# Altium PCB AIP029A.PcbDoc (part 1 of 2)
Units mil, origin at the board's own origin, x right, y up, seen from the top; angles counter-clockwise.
Board outline 1259.84 x 1259.84 mil, 4 copper layers (Top Layer, MidLayer1, MidLayer2, Bottom Layer), stack 40.8 mil thick; 91 components, 74 nets, 317 pads, 128 vias.
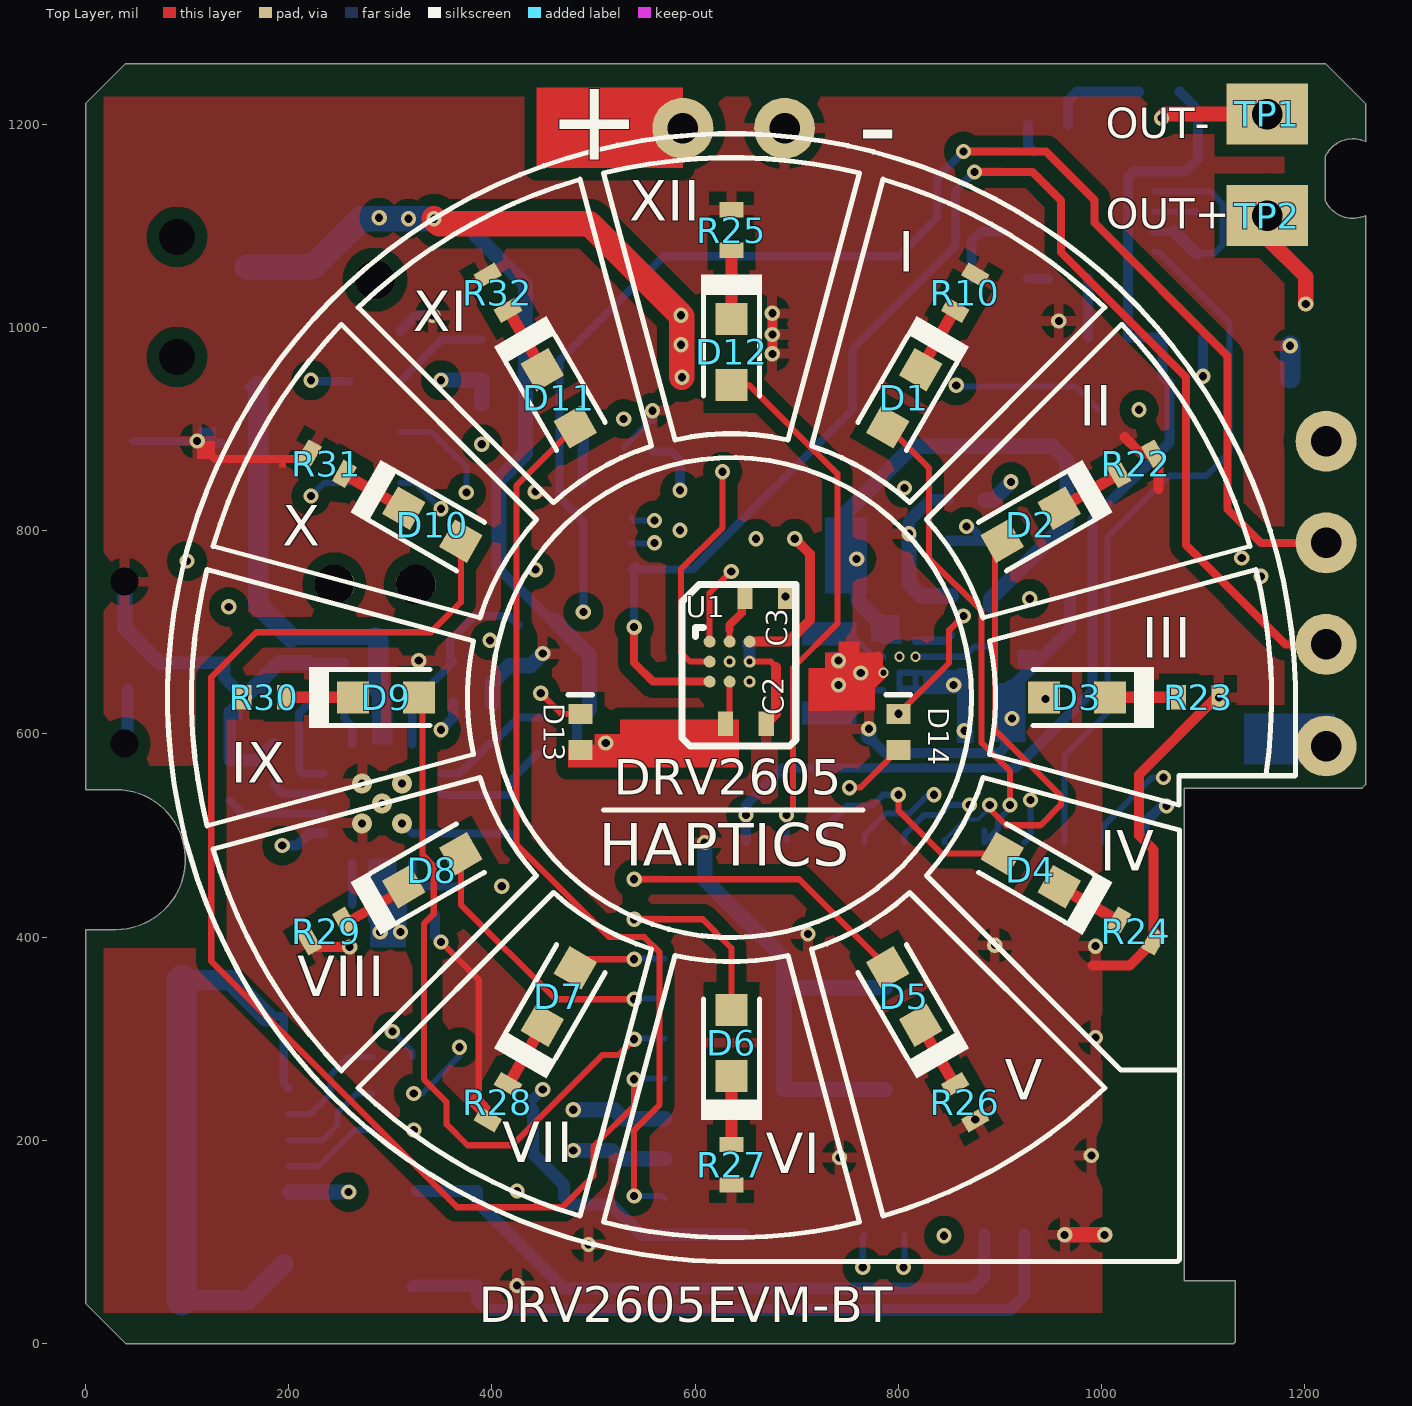
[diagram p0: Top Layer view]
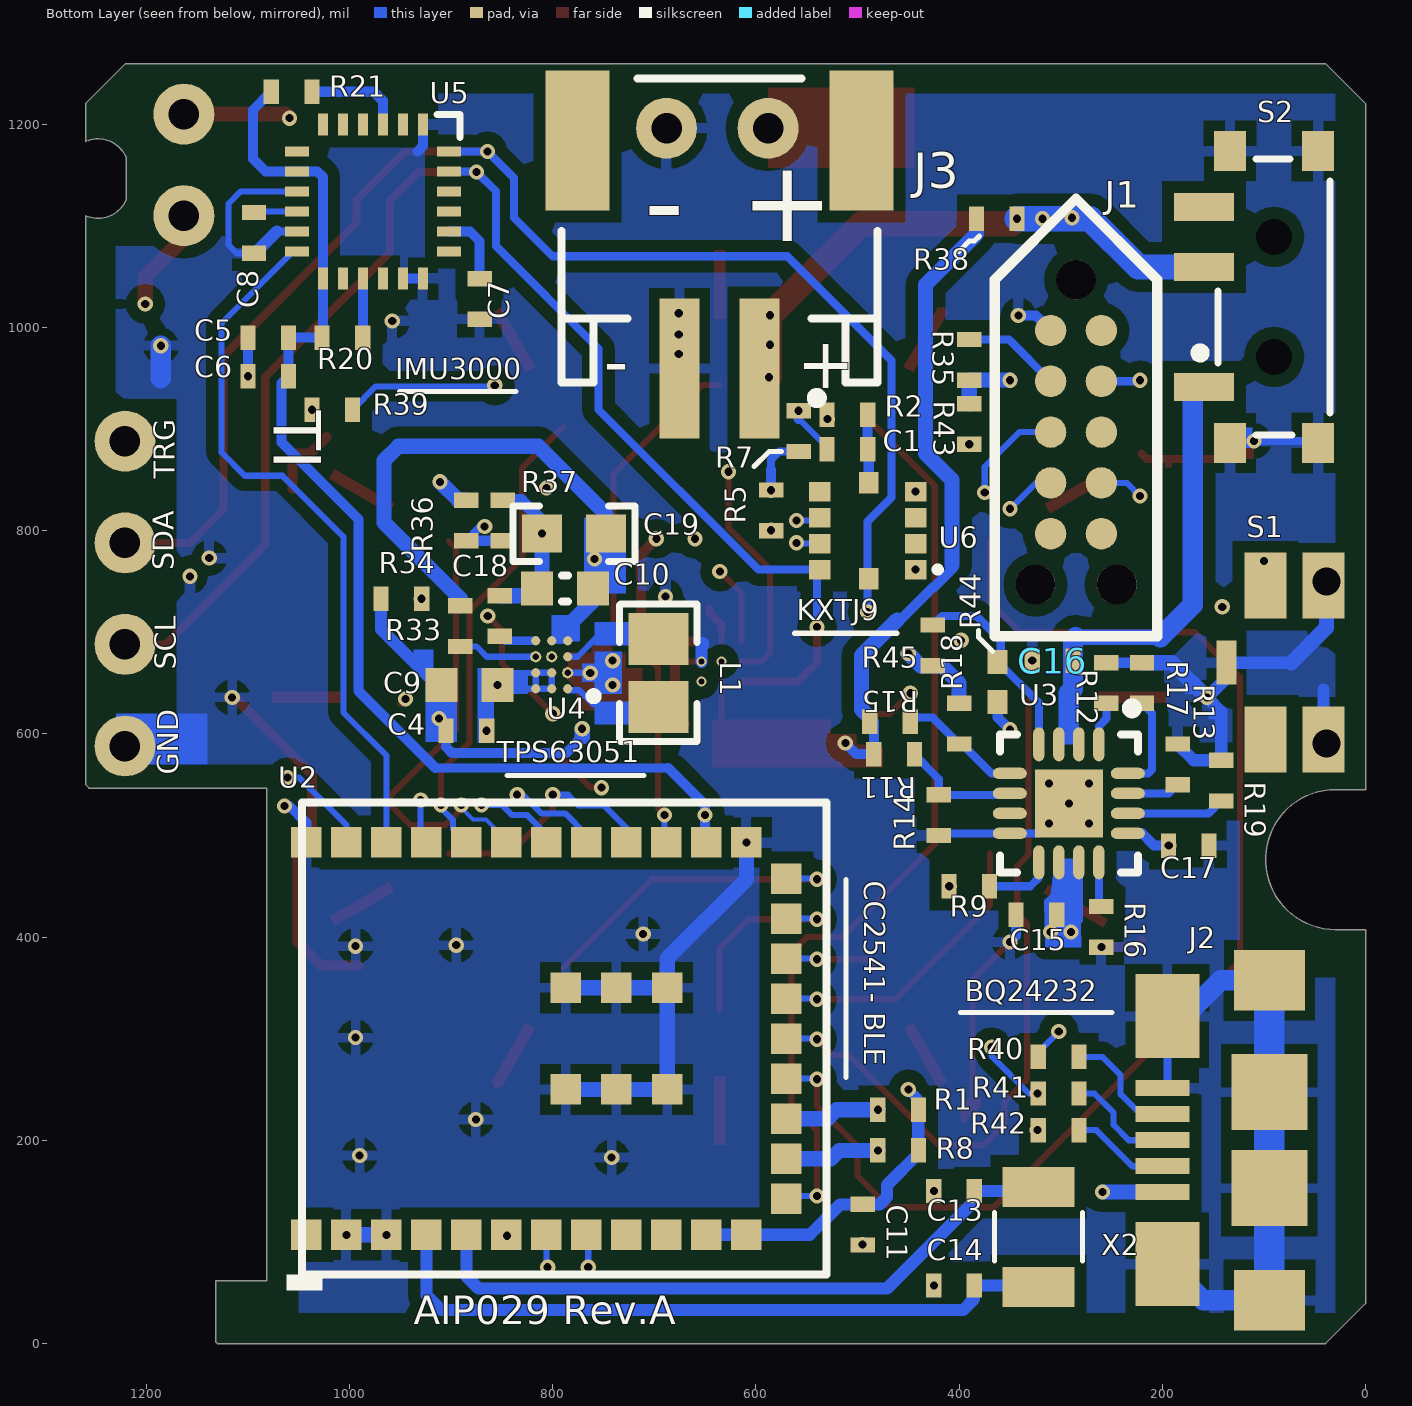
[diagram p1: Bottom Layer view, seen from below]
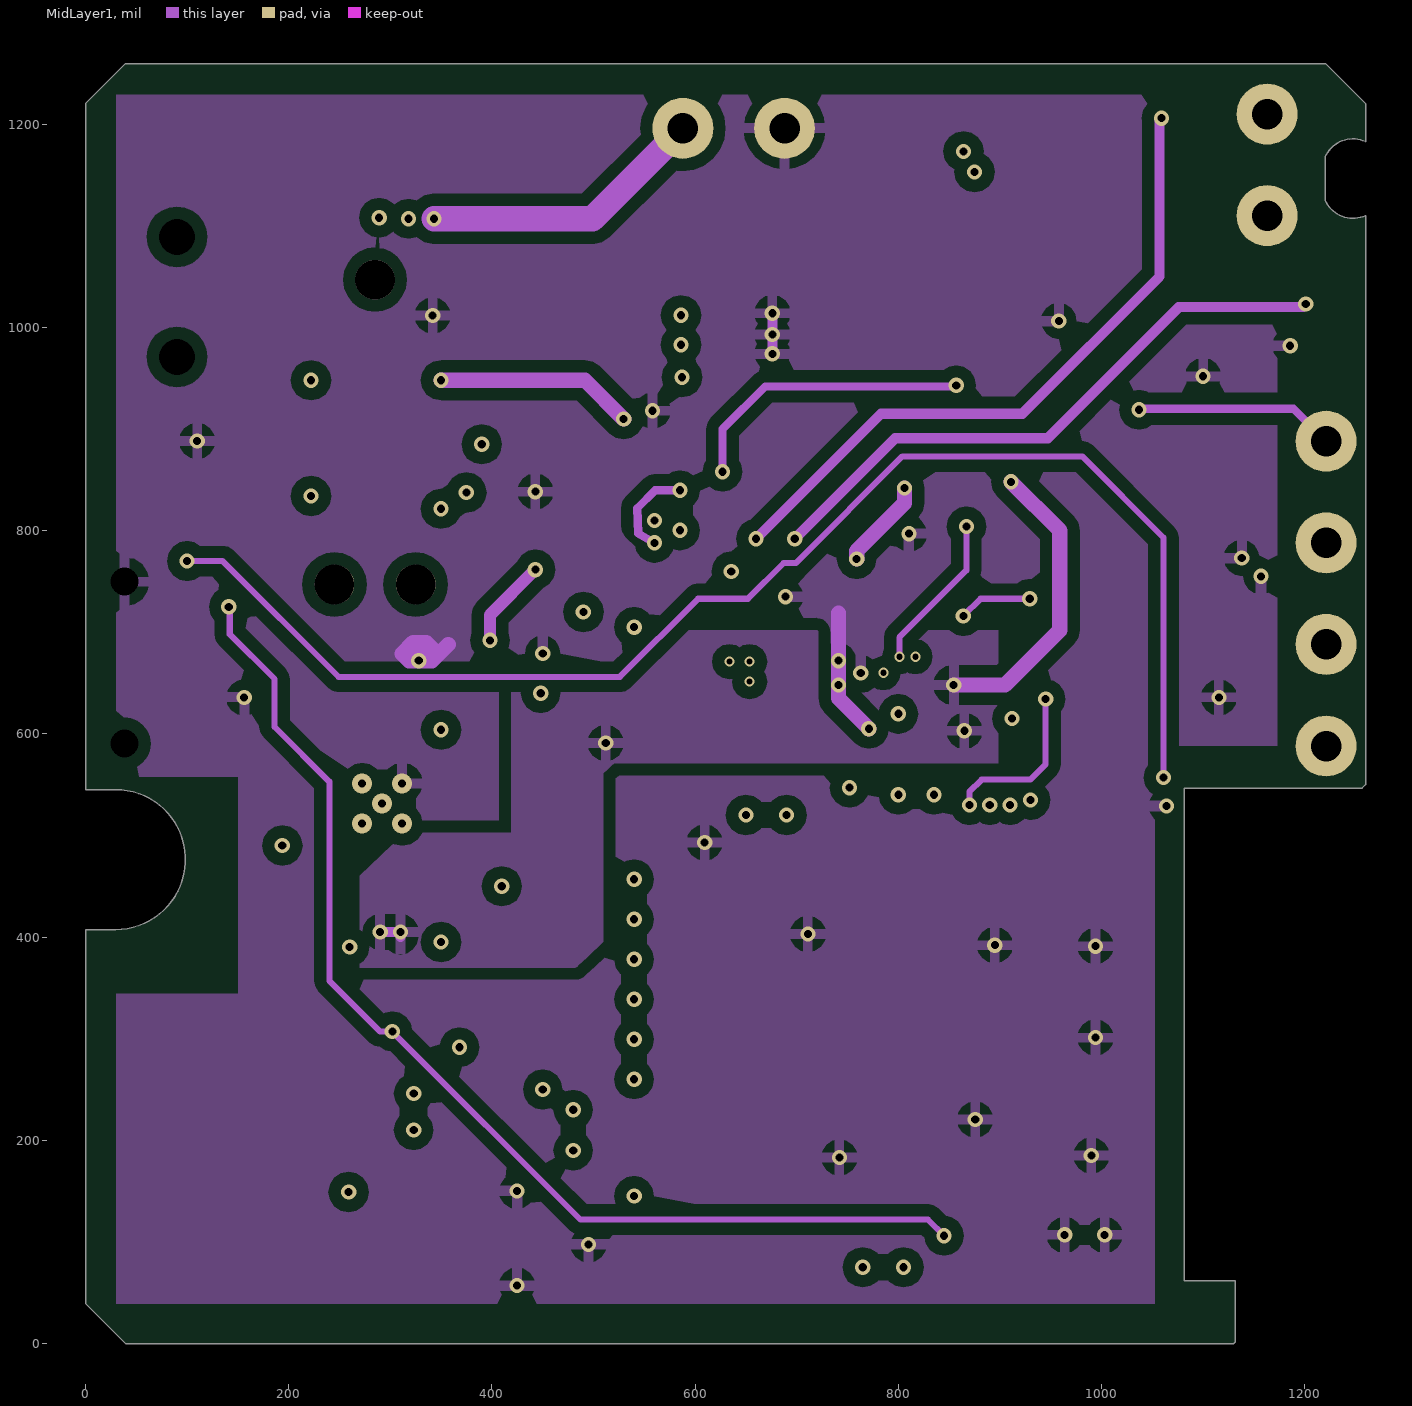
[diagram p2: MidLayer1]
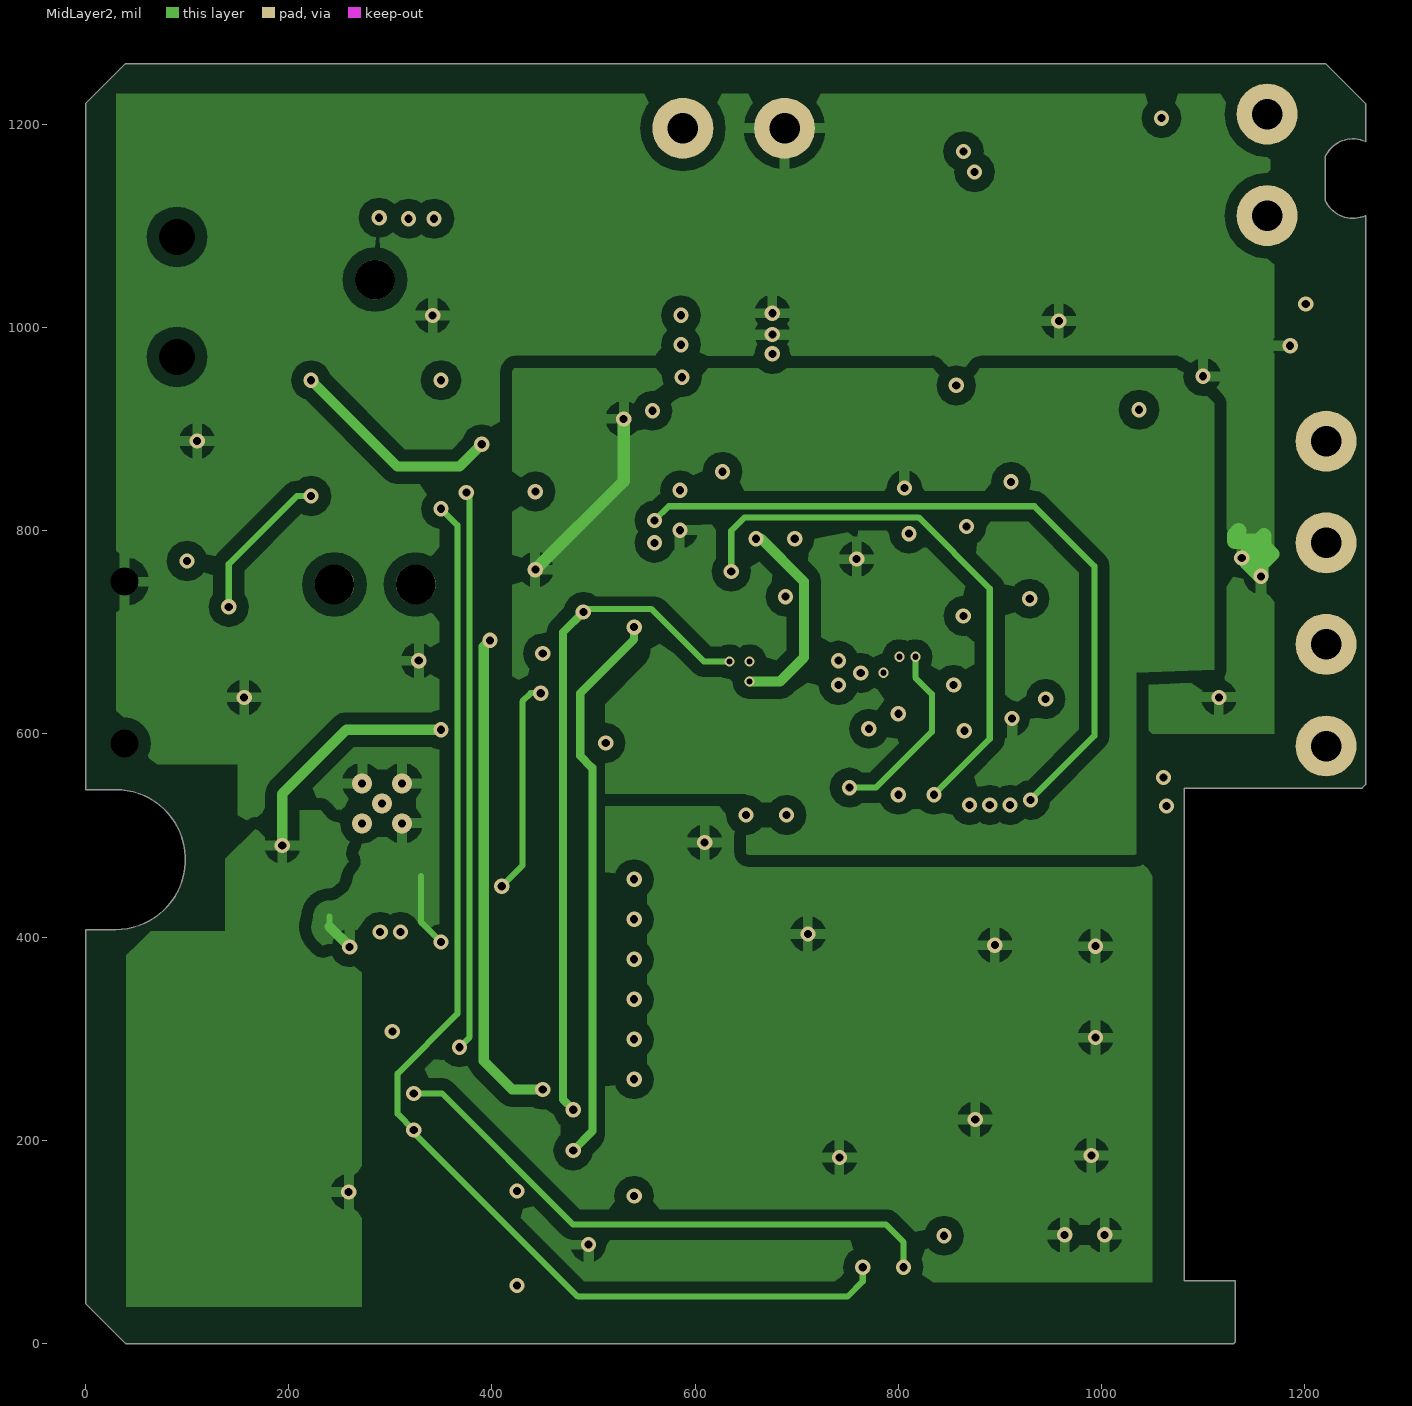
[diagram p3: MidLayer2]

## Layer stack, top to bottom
Top Layer: signal copper 1.4
Dielectric: core 10, FR-4, Dk 4.8
MidLayer1: signal copper 1.4
Dielectric: prepreg 12.6, FR-4, Dk 4.8
MidLayer2: signal copper 1.4
Dielectric: core 12.6, FR-4, Dk 4.8
Bottom Layer: signal copper 1.4

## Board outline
39.37,-0.09 1130.08,-0.09 1131.6,1.44 1131.6,61.6 1081.6,61.6 1081.6,546.6 1256.44,546.6 1259.84,550 1259.84,1110.04 cw(c1247.53,1137.6) 1219.97,1125.29 1219.97,1167.75 cw(c1247.53,1155.44) 1259.84,1183 1259.84,1220.39 1220.47,1259.76 39.37,1259.76 0,1220.39 0,545.19 29.53,545.19 cw(c29.53,476.29) 29.53,407.4 0,407.4 0,39.28

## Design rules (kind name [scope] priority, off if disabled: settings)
AcuteAngle [All] p1: minimum=4.50000000000000E+0001 checktracksonly=FALSE
AssemblyTestPointUsage [All] p1: valid=2
Clearance Clearance_BoardEdge_MountingHoles [OnCopper and InComponentClass('Mounting Holes') vs IsKeepOut] p1: gap=40
Clearance Clearance_BoardEdge_Poly [OnCopper and InPoly vs IsKeepOut] p2: gap=25
Clearance Clearance_BoardEdge [OnCopper and Not InComponentClass('Logo') and not InComponentClass('FiducialMark') and not InRegion(1000,500,4000,800) and Not IsKeepout vs IsKeepOut] p3: gap=75
Clearance Clearance_Poly [InPolygon] p4: gap=8
Clearance [All vs All and not S1] p5: gap=5
ComponentClearance ComponentClearance_1 [All] p1: gap=0 collisioncheckmode=3 verticalgap=0 showdistances=FALSE
ComponentClearance ComponentClearance_Shunt [InComponentClass('Header') vs InComponentClass('Shunt')] p2: gap=0 collisioncheckmode=3 verticalgap=0 showdistances=FALSE
ComponentClearance ComponentClearance_Logo [InComponentClass('Logo')] p3: gap=50 collisioncheckmode=3 verticalgap=10 showdistances=FALSE
ComponentClearance ComponentClearance_ScrewToNut [(HasFootprint('NY PMS 440 0025 PH')) vs (HasFootprint('Keystone_1902C'))] p4: gap=5 collisioncheckmode=3 verticalgap=10 showdistances=FALSE
ComponentClearance ComponentClearance_MountingHoles [InComponentClass('Mounting Holes')] p5: gap=250 collisioncheckmode=3 verticalgap=100000 showdistances=FALSE
ComponentClearance ComponentClearance_SmallPassives [HasFootprint('0201*') or HasFootprint('0402*') or HasFootprint('0508') or HasFootprint('0603*') or HasFootprint('0612') or HasFootprint('0805*') or HasFootprint('0815*') or HasFootprint('0830*') or HasFootprint('1206*') or HasFootprint('1210*') or HasFootprint('1808*') or HasFootprint('1812*') or HasFootprint('1825*') or HasFootprint('2010*') or HasFootprint('2220*') or HasFootprint('2225*') or HasFootprint('2512*') or HasFootprint('2728*') or HasFootprint('3518*') vs HasFootprint('0201*') or HasFootprint('0402*') or HasFootprint('0508') or HasFootprint('0603*') or HasFootprint('0612') or HasFootprint('0805*') or HasFootprint('0815*') or HasFootprint('0830*') or HasFootprint('1206*') or HasFootprint('1210*') or HasFootprint('1808*') or HasFootprint('1812*') or HasFootprint('1825*') or HasFootprint('2010*') or HasFootprint('2220*') or HasFootprint('2225*') or HasFootprint('2512*') or HasFootprint('2728*') or HasFootprint('3518*')] p6: gap=5 collisioncheckmode=3 verticalgap=-70 showdistances=FALSE
ComponentClearance ComponentClearance_THtoSMT [IsThruComponent vs IsSMTComponent] p7: gap=5 collisioncheckmode=3 verticalgap=5 showdistances=FALSE
ComponentClearance ComponentClearance_THtoTH [IsThruComponent vs IsThruComponent] p8: gap=5 collisioncheckmode=3 verticalgap=10 showdistances=FALSE
DiffPairsRouting [All] p1: maxlimit=100 minlimit=10 mostfreqgap=10 maxuncoupledlength=1000
FabricationTestPointUsage TestPointUsage [All] p1: valid=2 allowmultiple=FALSE
FabricationTestpoint Testpoint [All] p1: side=3 testpointundercomponent=TRUE minsize=40 maxsize=100 preferedsize=60 minholesize=0 maxholesize=40 preferedholesize=32 testpointgrid=1 allowsidetop=TRUE allowsidebottom=TRUE usegrid=TRUE gridtolerance=0.01
FanoutControl Fanout_LCC [IsLCC] p1: bgadir=Out bgaviamode=Centered fanoutstyle=Auto fanoutdirection=Alternating viagrid=1 // Fanout_LCC (Default Rule)
FanoutControl Fanout_BGA [IsBGA] p2: bgadir=Out bgaviamode=Centered fanoutstyle=Auto fanoutdirection=Alternating viagrid=1 // Fanout_BGA (Default Rule)
FanoutControl Fanout_Default [All] p4: bgadir=Out bgaviamode=Centered fanoutstyle=Auto fanoutdirection=Alternating viagrid=1 // Fanout_Default (Default Rule)
FanoutControl Fanout_Small [(CompPinCount < 5)] p5: bgadir=Out bgaviamode=Centered fanoutstyle=Auto fanoutdirection=OutThenIn viagrid=1 // Fanout_Small (Default Rule)
HoleSize [All] p1: absolutevalues=TRUE maxlimit=251 minlimit=3 maxpercent=80.000 minpercent=20.000
HoleToHoleClearance [All] p1: gap=9 allowstackedmicrovias=TRUE
MinimumAnnularRing MinimumAnnularRing_ThermalPadVias [IsVia and InAnyComponent] p1: minimumring=5.91
MinimumAnnularRing [All] p2: minimumring=2
MinimumSolderMaskSliver MinimumSolderMaskSliver_Logo [InComponentClass('Logo') vs InComponentClass('Logo')] p1: minsoldermaskwidth=0.7
MinimumSolderMaskSliver [All] p2: minsoldermaskwidth=4
PlaneClearance [All] p1: clearance=12
PlaneConnect [All] p1: planeconnectstyle=Relief reliefexpansion=10 reliefentries=4 reliefconductorwidth=10 reliefairgap=10
PolygonConnect [All] p1: connectstyle=Relief reliefconductorwidth=10 reliefentries=4 polygonreliefangle="90 Angle" airgapwidth=10
RoutingVias ThermalPadVias [IsVia and InAnyComponent] p1: holewidth=7.87 width=19.68 viastyle="Through Hole" minholewidth=7.87 minwidth=19.68 maxholewidth=12.99 maxwidth=23.62
RoutingVias [All] p2: holewidth=16 width=34 viastyle="Through Hole" minholewidth=5 minwidth=10 maxholewidth=40 maxwidth=65
SMDToCorner [All] p1: distance=1000
ShortCircuit [All] p1: allowed=TRUE
SilkToSilkClearance [All] p1: silktosilkclearance=0
SilkscreenOverComponentPads [All] p1: minsilkscreentomaskgap=-1
SolderMaskExpansion [All] p1: expansion=1
Width [All] p1: maxlimit=100 minlimit=3 preferedwidth=10 checkconnectedcopper=TRUE
11 further rules are at their usual default settings.

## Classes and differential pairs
component class AIP029A_Hardware: !PCB H1 H2 H3 H4 ZZ1 ZZ2
component class AssemblyNote: ZZ1 ZZ2

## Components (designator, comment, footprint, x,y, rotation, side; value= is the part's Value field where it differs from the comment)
C1 "GRM155R71C104KA88D" 0402S 510,880 r180 bottom
C2 "GRM155R71C104KA88D" 0402S 650,610 r0 top
C3 "GRM155R61A105KE15D" 0402S 669,735 r0 top
C4 "C1005X5R0J475M050BC" 0402S 885,603 r0 bottom
C5 "GRM155R71A104KA01D" 0402S 1080,990 r180 bottom
C6 "GRM155R71E103KA01D" 0402S 1080,952 r0 bottom
C7 "GRM155R71H222KA01D" 0402S 872,1028 r270 bottom
C8 "GRM155R71A104KA01D" 0402S 1094,1093 r270 bottom
C9 "C1608X5R1A106M" 0603L 882,648 r0 bottom
C10 "C1608X5R1A106M" 0603L 788,743 r0 bottom
C11 "C1005X7R1H104K" 0402S 495,117 r90 bottom
C13 "GRM1555C1H220JA01D" 0402S 405,150 r180 bottom
C14 "GRM1555C1H220JA01D" 0402S 405,57 r180 bottom
C15 "GRM155R61A475M" 0402S 324,422 r0 bottom
C16 "GRM155R61A475M" 0402S 308,672 r0 bottom
C17 "GRM155R61A105KE15D" 0402S 174,490 r180 bottom
C18 "C1005C0G1E102J" 0402S 852,716 r90 bottom
C19 "GRM188R60J476M" 0603 779,797 r0 bottom
D1 "SML312WBCW1" LED_SML 805.82,930.31 r60 top
D2 "SML312WBCW1" LED_SML 930.27,805.87 r30 top
D3 "SML312WBCW1" LED_SML 975.82,635.87 r0 top
D4 "SML312WBCW1" LED_SML 930.27,465.87 r330 top
D5 "SML312WBCW1" LED_SML 805.82,341.42 r300 top
D6 "SML312WBCW1" LED_SML 635.82,295.87 r270 top
D7 "SML312WBCW1" LED_SML 465.82,341.42 r240 top
D8 "SML312WBCW1" LED_SML 341.37,465.87 r210 top
D9 "SML312WBCW1" LED_SML 295.82,635.87 r180 top
D10 "SML312WBCW1" LED_SML 341.37,805.87 r150 top
D11 "SML312WBCW1" LED_SML 465.82,930.31 r120 top
D12 "SML312WBCW1" LED_SML 635.82,975.87 r90 top
D13 "SML-P12DTT86" LED_SMLP12_ORANGE 487,602 r90 top
D14 "SML-P12YTT86" LED_SMLP12_Yellow 800,602 r90 top
J1 "Used in BOM report" PCBComponent_1 364.99,696 r180 bottom
J2 "ZX62-B-5PA(11)" CONN_USB_micro_ZX62-B-5PA 200,200 r90 bottom
J3 "S2B-PH-SM4-TB(LF)(SN)" JST_S2B-PH-SM4-TB 635.82,1075.87 r0 bottom
L1 "LQM21PN1R0MC0D" 0805 696,660 r90 bottom
R1 "CRCW040210K0FKED" 0402S 460,230 r180 bottom
R2 "CRCW04020000Z0ED" 0402S 510,914 r0 bottom
R5 "CRCW04020000Z0ED" 0402S 585,820 r270 bottom
R7 "CRCW04020000Z0ED" 0402S 558,898 r270 bottom
R8 "CRCW040210K0FKED" 0402S 460,190 r180 bottom
R9 "CRCW04021K50FKED" 0402S 390,450 r0 bottom
R10 "CRCW040275R0FKED" 0402S 865.82,1034.24 r240 top
R11 "CRCW04020000Z0ED" 0402S 464,580 r0 bottom
R12 "CRCW040210K0FKED" 0402S 255,650 r270 bottom
R13 "CRCW04027K32FKED" 0402S 185,570 r270 bottom
R14 "CRCW04020000Z0ED" 0402S 420,520 r90 bottom
R15 "CRCW04020000Z0ED" 0402S 468,612 r0 bottom
R16 "CRCW040214K7FKED" 0402S 260,410 r90 bottom
R17 "CRCW04028K66FKED" 0402S 220,650 r270 bottom
R18 "CRCW04020000Z0ED" 0402S 400,610 r270 bottom
R19 "CRCW04020000Z0ED" 0402S 142,554 r270 bottom
R20 "CRCW04020000Z0ED" 0402S 1007,990 r180 bottom
R21 "CRCW04020000Z0ED" 0402S 1057,1232 r0 bottom
R22 "CRCW040275R0FKED" 0402S 1034.19,865.87 r210 top
R23 "CRCW040275R0FKED" 0402S 1095.82,635.87 r180 top
R24 "CRCW040275R0FKED" 0402S 1034.19,405.87 r150 top
R25 "CRCW040275R0FKED" 0402S 635.82,1095.87 r270 top
R26 "CRCW040275R0FKED" 0402S 865.82,237.49 r120 top
R27 "CRCW040275R0FKED" 0402S 635.82,175.87 r90 top
R28 "CRCW040275R0FKED" 0402S 405.82,237.49 r60 top
R29 "CRCW040275R0FKED" 0402S 237.45,405.87 r30 top
R30 "CRCW040275R0FKED" 0402S 175.82,635.87 r0 top
R31 "CRCW040275R0FKED" 0402S 237.45,865.87 r330 top
R32 "CRCW040275R0FKED" 0402S 405.82,1034.24 r300 top
R33 "CRCW040210K0FKED" 0402S 891,706 r90 bottom
R34 "CRCW04021K50FKED" 0402S 949,733 r180 bottom
R35 "CRCW04020000Z0ED" 0402S 390,968 r270 bottom
R36 "CRCW04020000Z0ED" 0402S 885,810 r90 bottom
R37 "CRCW04020000Z0ED" 0402S 849,810 r270 bottom
R38 "CRCW04020000Z0ED" 0402S 363,1107 r0 bottom
R39 "CRCW04020000Z0ED" 0402S 1017,919 r0 bottom
R40 "CRCW04020000Z0ED" 0402S 302,282 r0 bottom
R41 "CRCW04020000Z0ED" 0402S 302,246 r0 bottom
R42 "CRCW04020000Z0ED" 0402S 302,210 r0 bottom
R43 "CRCW04020000Z0ED" 0402S 390,905 r90 bottom
R44 "CRCW04020000Z0ED" 0402L 362,651 r270 bottom
R45 "CRCW04020000Z0ED" 0402S 426,687 r90 bottom
S1 "PTS840 PM SMTR LFS" "SW_PTS840 P" 70,670 r90 bottom locked
S2 "EG1257" SW_EG1257 90,1030 r90 bottom
TP1 "" DUMMY-PAD 1163,1210 r180 top
TP2 "" DUMMY-PAD 1163,1110 r180 top
U1 "DRV2605YZF" YZF0009ADAD 633.96,671.04 r0 top
U2 "450-0103" TiWi-uB1 570,300 r90 bottom
U3 "BQ24232RGTR" RGT0016C 292.02,531.6 r270 bottom
U4 "TPS63051YFF" YFF0012AFAF 801,668 r0 bottom
U5 "IMU-3000" QFN50P400X400X95-24N 977,1124 r270 bottom
U6 "KXTJ9-1007" LGA3X3MM_0.65 490,800 r0 bottom
X2 "NX3215SA-32.768K-STD-MUS-2" XTAL_NX3215SA 322,105 r270 bottom
ZZ1 "CE Logo" AssemblyNote 212,2423 r0 top
ZZ2 "These assemblies are ESD sensitive, ESD precautions shall be observed." AssemblyNote 193,2235 r0 top

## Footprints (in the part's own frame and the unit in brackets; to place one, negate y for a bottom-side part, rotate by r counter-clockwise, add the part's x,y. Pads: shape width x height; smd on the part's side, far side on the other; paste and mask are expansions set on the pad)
0402L [mm] "0402 from SM-752 data"
  rect 0.6x0.5 smd: 1(-0.5,0) 2(0.5,0)
  body extent -0.55,-0.3 0.55,0.3, height 0.6
0402S [mil] "Based on C0402S footprint from PADS legacy"
  rect 15x24 smd: 1(-20,0) 2(20,0)
  body extent -22,-12 22,12, height 24
0603 [mm] "0603 from SM-752 data"
  rect 1x0.95 smd: 1(-0.8,0) 2(0.8,0)
  silkscreen extent -1.52,-0.69 1.52,0.69, body extent -0.87,-0.47 0.87,0.47, height 0.85
0603L [mm] "0603 from SM-752 data"
  rect 0.8x0.85 smd: 1(-0.7,0) 2(0.7,0)
  body extent -0.87,-0.47 0.87,0.47, height 0.85
0805 [mm] "0805 from SM-752 data"
  rect 1.3x1.5 smd: 1(-0.85,0) 2(0.85,0)
  silkscreen extent -1.72,-0.97 1.72,0.97, body extent -1.1,-0.72 1.1,0.72, height 1.1
AssemblyNote [mil] "Assembly Note"
CONN_USB_micro_ZX62-B-5PA [mm] "Hirose"
  rect 0.4x1.35 smd: 1(-1.3,0) 2(-0.65,0) 3(0,0) 4(0.65,0) 5(1.3,0)
  rect 1.9x1.9 smd: 6(-1.2,-2.675) 7(1.2,-2.675)
  rect 1.524x1.778 smd: 8(-4,-2.675) 9(4,-2.675)
  rect 2.1x1.6 smd: 10(-3.1,-0.125) 11(3.1,-0.125)
  body extent -3.75,-5.32 3.75,0.18, height 2.55
DUMMY-PAD [mil]
  rect 80x60 smd: 1(0,0)
JST_S2B-PH-SM4-TB [mm] "JST Sales America Inc"
  rect 1x3.5 smd paste+0: 1(-1,2.95)
  rect 1x3.5 smd: 2(1,2.95)
  rect 1.6x3.5 smd paste+0 mask+0.05: M1(-3.55,-2.75) M2(3.55,-2.75)
  silkscreen extent -3.95,-4.3 3.95,3.79, body extent -3.95,-4.3 3.95,4.3, height 5.62
LED_SML [mm] "Rohm"
  rect 0.8x0.8 smd: 1(-0.825,0) 2(0.825,0)
  silkscreen extent -1.1,-0.76 1.93,0.76, body extent -0.8,-0.4 0.8,0.4, height 0.9
LED_SMLP12_ORANGE [mm] "Rohm Semiconductor"
  rect 0.5x0.6 smd mask+0.08: 1(-0.45,0) 2(0.45,0)
  silkscreen extent 0.92,-0.3 0.92,0.3, body extent -0.55,-0.35 0.55,0.35, height 0.25
LED_SMLP12_Yellow [mm] "Rohm Semiconductor"
  rect 0.5x0.6 smd mask+0.08: 1(-0.45,0) 2(0.45,0)
  silkscreen extent 0.92,-0.3 0.92,0.3, body extent -0.55,-0.35 0.55,0.35, height 0.25
LGA3X3MM_0.65 [mm] "KIONIX"
  rect 0.54x0.49 smd paste-0.092 mask-0.07: 1(-1.2,0.975) 2(-1.2,0.325) 3(-1.2,-0.325) 4(-1.2,-0.975) 6(1.2,-0.975) 7(1.2,-0.325) 8(1.2,0.325) 9(1.2,0.975)
  rect 0.49x0.54 smd paste-0.092 mask-0.07: 5(-0.025,-1.2) 10(-0.025,1.2)
  silkscreen extent -1.77,0.95 -1.73,1, body extent -1.55,-1.55 1.55,1.55, height 1.02
PCBComponent_1 [mil]
  round 30.98 smd paste+0 mask+1.5: 1(55.04,301) 2(55.04,251) 3(55.04,201) 4(55.04,151) 5(55.04,101) 6(105.04,101) 7(105.04,151) 8(105.04,201) 9(105.04,251) 10(105.04,301)
  round 39.02 hole 39.02 unplated mask+1.5: ""(40.08,51) ""(80.04,351) ""(120,51)
  silkscreen extent 0,0 160,431
QFN50P400X400X95-24N [mm] "QFN, 24-Leads, Body 4.1x4.1mm (max), Pitch 0.50mm"
  rect 0.55x0.25 smd mask+0.05: 1(-1.925,1.25) 2(-1.925,0.75) 3(-1.925,0.25) 4(-1.925,-0.25) 5(-1.925,-0.75) 6(-1.925,-1.25) 13(1.925,-1.25) 14(1.925,-0.75) 15(1.925,-0.25) 16(1.925,0.25) 17(1.925,0.75) 18(1.925,1.25)
  rect 0.25x0.6 smd mask+0.05: 7(-1.25,-1.9) 8(-0.75,-1.9) 9(-0.25,-1.9) 10(0.25,-1.9) 11(0.75,-1.9) 12(1.25,-1.9) 19(1.25,1.9) 20(0.75,1.9) 21(0.25,1.9) 22(-0.25,1.9) 23(-0.75,1.9) 24(-1.25,1.9)
  silkscreen extent -2.17,1.6 -1.6,2.17, body extent -2.05,-2.05 2.05,2.05, height 0.95
RGT0016C [mm] "QFN, 16-Leads, Body 3x3mm, Pitch 0.5mm, Thermal Pad 1.7x1.7mm, TI Recommended"
  oval 0.85x0.28 smd paste-0.025: 1(-1.475,0.75) 2(-1.475,0.25) 3(-1.475,-0.25) 4(-1.475,-0.75) 9(1.475,-0.75) 10(1.475,-0.25) 11(1.475,0.25) 12(1.475,0.75)
  oval 0.28x0.85 smd paste-0.025: 5(-0.75,-1.475) 6(-0.25,-1.475) 7(0.25,-1.475) 8(0.75,-1.475) 13(0.75,1.475) 14(0.25,1.475) 15(-0.25,1.475) 16(-0.75,1.475)
  rect 1.7x1.7 smd paste-0.85 mask+0.07: 17(0,0)
  silkscreen extent -2.5,-1.73 1.73,1.73, body extent -1.57,-1.57 1.58,1.58, height 1
SW_EG1257 [mm] "E-SWITCH"
  rect 0.7x1.5 smd: 1(-2.25,1.75) 2(0.75,1.75) 3(2.25,1.75)
  rect 1x0.8 smd: 4(-3.65,-1.1) 5(-3.65,1.1) 6(3.65,-1.1) 7(3.65,1.1)
  round 0 hole 0.9 unplated: MH-1(-1.5,0) MH-1(1.5,0)
  silkscreen extent -3.45,-1.4 3.45,1.97, body extent -3.9,-2.85 3.9,2.2, height 1.6
"SW_PTS840 P" [mm] "C&K"
  rect 1.65x1.05 smd: 1(-1.925,0.725) 2(1.925,0.725) 3(-1.925,-0.725) 4(1.925,-0.725)
  rect 1.1x0.5 smd: 5(0,1.7)
  round 0 hole 0.7: MH1(-2.025,-0.8) MH2(2.025,-0.8)
  body extent -1.75,-2.1 1.75,1.45, height 1.35
TiWi-uB1 [mm] "Bluetooth Module"
  rect 0.76x0.76 smd: 1(-4.905,12) 2(-4.905,11) 3(-4.905,10) 4(-4.905,9) 5(-4.905,8) 6(-4.905,7) 7(-4.905,6) 8(-4.905,5) 9(-4.905,4) 10(-4.905,3) 11(-4.905,2) 12(-4.905,1) 13(-4,0) 14(-3,0) 15(-2,0) 16(-1,0) 17(0,0) 18(1,0) 19(2,0) 20(3,0) 21(4,0) 22(4.905,1) 23(4.905,2) 24(4.905,3) 25(4.905,4) 26(4.905,5) 27(4.905,6) 28(4.905,7) 29(4.905,8) 30(4.905,9) 31(4.905,10) 32(4.905,11) 33(4.905,12) 34(-1.27,5.52) 35(-1.27,4.25) 36(-1.27,2.98) 37(1.27,5.52) 38(1.27,4.25) 39(1.27,2.98)
  silkscreen extent -6.3,-1 5.9,12.5, body extent -5.82,-0.91 5.77,16.99, height 2.2
XTAL_NX3215SA [mm] "NDK recommended land pattern"
  rect 1x1.8 smd: 1(-1.25,0) 2(1.25,0)
  silkscreen extent -0.6,-1.1 0.6,1.1, body extent -1.65,-0.8 1.65,0.8, height 0.9
YFF0012AFAF [mm] "TI DSBGA 1.716x1.316mm"
  round 0.23 smd paste-0.13 mask+0: A1(-0.4,0.6) A2(0,0.6) A3(0.4,0.6) B2(0,0.2) B3(0.4,0.2) C1(-0.4,-0.2) D1(-0.4,-0.6) D2(0,-0.6) D3(0.4,-0.6)
  round 0.28 smd paste-0.13 mask+0: B1(-0.4,0.2) C2(0,-0.2) C3(0.4,-0.2)
  silkscreen extent -1.15,0.69 -0.95,0.89, body extent -0.66,-0.86 0.66,0.86, height 0.63
YZF0009ADAD [mm] "WCSP"
  round 0.3 smd paste-0.15 mask+0: A1(-0.5,0.5) A2(0,0.5) A3(0.5,0.5) B1(-0.5,0) B2(0,0) B3(0.5,0) C1(-0.5,-0.5) C2(0,-0.5) C3(0.5,-0.5)
  silkscreen extent -0.85,0.63 -0.65,0.85, body extent -0.73,-0.73 0.73,0.73, height 0.63

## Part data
C1 C2: "CAP, CERM, 0.1uF, 16V, +/-10%, X7R, 0402"
C3 C17: "CAP, CERM, 1uF, 10V, +/-10%, X5R, 0402"
C4: "CAP, CERM, 4.7uF, 6.3V, +/-20%, X5R, 0402"
C5 C8: "CAP, CERM, 0.1uF, 10V, +/-10%, X7R, 0402"
C6: "CAP, CERM, 0.01uF, 25V, +/-10%, X7R, 0402"
C7: "CAP, CERM, 2200pF, 50V, +/-10%, X7R, 0402"
C9 C10: "CAP, CERM, 10uF, 10V, +/-20%, X5R, 0603"
C11: "CAP, CERM, 0.1uF, 50V, +/-10%, C0G/NP0, 0402"
C13 C14: "CAP, CERM, 22pF, 50V, +/-5%, C0G/NP0, 0402"
C15 C16: "CAP, CERM, 4.7uF, 10V, +/-20%, X5R, 0402"
C18: "CAP, CERM, 1000pF, 25V, +/-5%, C0G/NP0, 0402"
C19: "CAP, CERM, 47uF, 6.3V, +/-20%, X5R, 0603"
D1 D2 D3 D4 D5 D6 D7 D8 D9 D10 D11 D12: "LED, White, SMD"
D13: "LED, Orange, SMD"
D14: "LED, Yellow, SMD"
J1: library part Component_1
J2: "Connector, micro USB Type B, Receptacle, R/A, SMD"
J3: "Header, 2x1,2mm, R/A, SMT"
L1: "Inductor, Multilayer, Ferrite, 1uH, 0.8A, 0.19 ohm, SMD"
R1 R8 R12 R33: "RES, 10.0k ohm, 1%, 0.063W, 0402"
R2 R5 R7 R11 R14 R15 R18 R19 R20 R21 R35 R36 R37 R38 R39 R40 R41 R42 R43 R44 R45: "RES, 0 ohm, 5%, 0.063W, 0402"
R9 R34: "RES, 1.50k ohm, 1%, 0.063W, 0402"
R10 R22 R23 R24 R25 R26 R27 R28 R29 R30 R31 R32: "RES, 75.0 ohm, 1%, 0.063W, 0402"
R13: "RES, 7.32k ohm, 1%, 0.063W, 0402"
R16: "RES, 14.7k ohm, 1%, 0.063W, 0402"
R17: "RES, 8.66k ohm, 1%, 0.063W, 0402"
S1: "SWITCH TACTILE SPST-NO 0.05A 12V, SMT"
S2: "Switch, Slide, SPDT, 0.3A, SMT"
TP1 TP2: library part DUMMY-PIN, "PAD, 5X5mm"
U1: "Haptic Driver for ERM and LRA with Built-In Library and Smart Loop Architecture, YZF0009ADAD"
U2: library part TiWi-uB1, "BLUETOOTH SMART (BLE) MODULE"
U3: "USB Friendly 0.5 A Li+ Charger with Dynamic Power Management, 10.5 V OVP, 4.3 V, -40 to 85 degC, 16-pin QFN (RGT), Green (RoHS & no Sb/Br)"
U4: "SINGLE INDUCTOR BUCK-BOOST WITH 1A SWITCHES AND ADJUSTABLE SOFT START, YFF0012AFAF"
U5: "Motion Processing Unit, QFN-24"
U6: "± 2g / 4g / 8g Tri-axis Digital Accelerometer, SMT"
X2: "Crystal, 32.768kHz, 12.5pF, SMD"
ZZ1 ZZ2: library part AssemblyNote

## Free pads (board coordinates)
  round 60 hole 30: 0(588,1196) 0(688,1196) 0(1163,1110) 0(1163,1210) 0(1221,588) 0(1221,688) 0(1221,788) 0(1221,888)

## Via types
v1: diameter 15, hole 8, Top Layer to Bottom Layer, tented both sides, 116 vias
v2: diameter 19.68, hole 7.87, Top Layer to Bottom Layer, tented top, 5 vias
v3: diameter 10, hole 6, Top Layer to Bottom Layer, tented top, 3 vias
v4: diameter 10, hole 6, Top Layer to Bottom Layer, tented bottom, 3 vias
v5: diameter 15, hole 8, Top Layer to Bottom Layer, tented top, 1 vias

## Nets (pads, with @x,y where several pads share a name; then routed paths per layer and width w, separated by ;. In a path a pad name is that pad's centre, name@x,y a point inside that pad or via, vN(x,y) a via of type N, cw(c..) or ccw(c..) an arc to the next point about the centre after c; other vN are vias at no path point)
DC: J1.3 R41.2 U2.7 | length 1323.1
  MidLayer2 w6: v1(323,246) 351,246 480,117 788,117 805,100 v1(805,75) ; v1(368,291.5) 378,301.5 378,834.3 v1(374.8,837.5)
  Bottom Layer w6: J1.3@309.95,897 340.7,897 374.8,862.9 v1(374.8,837.5) ; v1(323,246) 331.5,246 368,282.5 v1(368,291.5) ; v1@806.22,76.22 U2.7@806.22,106.89
DD: J1.4 R42.2 U2.8 | length 1261.4
  MidLayer2 w6: v1@323,207.56 484.56,46 750,46 765,61 v1(765,75) ; v1(323,210) 307.1,225.9 307.1,265.4 366,324.3 366,805.3 v1(349.8,821.5)
  Bottom Layer w6: J1.4@309.95,847 324.3,847 v1(349.8,821.5) ; v1(765,75) 765,105.04 U2.8@766.85,106.89
DRV_EN: U1.A1 U2.26 | length 724.6
  Top Layer w6: U1.A1@614.28,690.72 614.28,738.61 v1(635.54,759.88)
  MidLayer2 w6: v1(635.54,759.88) 635.54,799.88 648.66,813 820,813 890,743 890,595 v1(835,540)
  Bottom Layer w6: U2.26@766.85,493.11 766.85,500.62 787.89,521.66 811.1,521.66 829.44,540 v1(835,540)
DRV_TRIG: pad.0@1221,888 R39.2 | length 197.3
  MidLayer1 w8: v1@1037,920 1189,920 pad.0@1221,888
  other v1: 1037,919
GND: C1.1 C2.2 C3.2 C4.2 C5.1 C6.2 C7.2 C8.2 C9.2 C10.2 C11.1 C13.1 C14.1 C15.2 C16.2 C17.2 C18.2 C19.2 J1.1 J2.5 J2.6 J2.7 J2.8 J2.9 J2.10 J2.11 J3.2 pad.0@688,1196 pad.0@1221,588 R7.1 R10.1 R12.1 R13.1 R14.1 R16.1 R17.1 R18.1 R19.1 R22.1 R23.1 R24.1 R25.1 R26.1 R27.1 R28.1 R29.1 R30.1 R31.1 R32.1 R34.1 R37.1 R45.1 S1.3 S1.4 S1.5 S2.4 S2.5 S2.6 S2.7 U1.B3 U2.2 U2.3 U2.22 U2.33 U2.34 U2.35 U2.36 U2.37 U2.38 U2.39 U3.8 U3.17 U4.B1 U5.1 U5.9 U5.11 U5.17 U5.18 U6.4 | length 4626.1
  Top Layer w6: v1(350,395) 387,358 387,246.33 ; 389.88,232.3 393.14,232.3 ; R28.1@395.97,220.45 R28.1@395.82,220.6 ; v4(653.65,671.04) 674.43,671.04 679.55,665.92 ; v1(763,660) 763.13,660.13 780,660.13 v3(785.25,660.13) ; 387,241.12 387,246.33 ; 387,241.12 387,229.42 R28.1@393.14,223.28 ; 387,241.12 393.14,234.98 393.14,232.3 ; 387,246.33 381.39,240.72 381.39,234.6 R28.1@393.14,222.85 ; R28.1@393.14,222.85 R28.1@393.14,223.28 ; R28.1@393.14,222.85 R28.1@395.82,220.17 R28.1@395.82,220.6 ; R28.1@393.14,223.28 393.14,232.3 ; R28.1@393.14,223.28 R28.1@395.82,220.6 ; 393.14,232.3 395.82,232.3 R28.1@395.82,220.6
  Top Layer w8: v1(109.88,888.24) 127.62,870.5 215.19,870.5 R31.1@220.4,875.71
  Top Layer w10: R29.1@220.4,396.02 226.11,390.32 v1(260,390.32) ; C2.2@670,610 679.55,619.55 679.55,665.92 ; v1(676,974) v1(676,993) v1(676,1014) ; 991.16,371.86 1027.5,371.86 R24.1@1051.51,395.87 ; 1022.8,891.85 1038.78,875.87 R22.1@1051.51,875.87 1056,871.38 1056,841 ; R24.1@1051.24,396.02 1051.24,485.76 1037,500 1037,560 1112.87,635.87 v1(1115.5,635.87) ; 780,665.38 780,660.13 780,655 775,650 775,649.87 v3(785.25,660.13) 780,665.38 ; 780,665.38 780,675.87 779.93,675.87 775.94,671.89 775.94,669.44 780,665.38
  Top Layer w15: v1@768,660 v1(763,660) 753,660 ; v1(963.7,106.89) v1(1003.07,106.89) ; 753,660 v1(741,672) v1(741,648) 753,660
  MidLayer1 w8: v2@272.33,550.31 v2(272.33,551.29)
  MidLayer1 w10: v1(676,974) v1(676,993) v1(676,1014)
  MidLayer1 w15: 327.67,680.67 344.48,680.67 335.32,689.84 322.53,689.84 311.52,678.83 ; 357,688 341,672 v1(328,672) ; 741,719 v1(741,672) v1(741,648) 741,635 v1(771,605) ; 311.52,678.83 318.34,672 v1(328,672) ; 311.52,678.83 321.17,678.83 v1(328,672)
  MidLayer2 w6: 240,410.32 240,420 ; 330,460 330,415 v1(350,395) ; v1(1138,773) v1@1139,773
  MidLayer2 w10: 240,410.32 v1(260,390.32)
  MidLayer2 w15: 1135,800 1131.17,796.17 1131.17,789.48 1144.83,789.48 ; v1@1139,773 1144.83,767.17 ; 1144.83,767.17 1144.83,789.48 ; 1144.83,767.17 v1(1157,755) 1157,766.48 ; 1144.83,789.48 1154.48,789.48 1160,795 1160,784.46 1167.49,776.97 1157,766.48 ; 1144.83,789.48 1157,777.31 1157,766.48
  Bottom Layer w4: C1.1@530,880 C1.1@530,882
  Bottom Layer w6: C1.1@530,882 558,910 ; v1@744,672 756,660 v1(763,660) v1@768,660 ; v1@768.13,660.13 v3(785.25,660.13) ; U5.9@1051.8,1133.84 1107.16,1133.84 1119,1122 1119,1081 1111,1073 C8.2@1094,1073
  Bottom Layer w8: S2.4@46.69,888.24 v1(109.88,888.24) ; J2.11@177.95,322.05 J2.11@195.08,322.05 195.08,256.1 J2.5@200,251.18 ; v2(311.7,511.91) 321.55,502.07 U3.8@350.09,502.07 417.93,502.07 R14.1@420,500 ; U5.11@1051.8,1094.47 1071.53,1094.47
  Bottom Layer w10: v1(109.88,888.24) 111.82,886.3 S2.5@133.31,886.3 ; R17.1@220,670 R12.1@255,670 ; J1.1@309.95,997 324.64,1011.69 v1(341.69,1011.69) ; C15.2@344,422 344,401 v1(350,395) ; 558,910 v1(558,918) ; 771,597 787,581 899,581 905,587 C4.2@905,603 ; C9.2@909.56,648 C9.2@914,648 ; U5.18@927.79,1048.21 U5.17@947.47,1048.21 ; U5.1@927.79,1199.79 927.79,1178.43 933,1173.21 ; U2.33@1042.44,493.11 1042.44,512.44 1059,529 v1(1064,529) ; v1(1100,952) C5.1@1100,990
  Bottom Layer w12: S1.3@41.46,594.21 41.46,643.54 ; 73,670 S1.5@136.93,670 136.93,655.07 v1(156.13,635.87) 142,621.73 R19.1@142,574 169,574 R13.1@185,590 ; 652.09,689.41 652.09,686.91 653.65,685.35 v4(653.65,671.04) ; v1(810.5,797) 810.5,809.5 831,830 R37.1@849,830 ; C9.2@914,648 969,703 R34.1@969,733 ; 1071.53,1094.47 1093,1073 C8.2@1094,1073
  Bottom Layer w15: S1.4@38.5,749.72 38.5,704.5 73,670 ; v1(156.13,635.87) 190.27,670 R17.1@220,670 ; R18.1@400,630 400,650 417,667 R45.1@426,667 438,667 v1(450,679) ; v1(609.37,493.11) 609.37,456.63 687.32,378.68 U2.39@687.32,350 ; 771,597 v1(771,605) ; U2.34@787.32,250 U2.35@737.32,250 U2.36@687.32,250 U2.39@687.32,350 ; U2.37@787.32,350 U2.38@737.32,350 U2.39@687.32,350 ; v1(810.5,797) 810.5,748.06 C10.2@815.56,743 822.56,736 C18.2@852,736 ; v1(963.7,106.89) v1(1003.07,106.89)
  Bottom Layer w20: J2.8@94.68,42.52 159.65,42.52 J2.10@195.08,77.95 ; J2.9@94.68,357.48 142.52,357.48 J2.11@177.95,322.05 ; 1185.68,950 v1(1185.68,982)
  Bottom Layer w30: J2.8@94.68,42.52 J2.7@94.68,247.24 J2.9@94.68,357.48
  other v1: 424.68,57 495,97.32 424.68,150 742,183 990,185 875.66,220.45 994,301 994,391 895,392 711,403 912,615 689,735 442.76,838.39 958,1006.31
  other v2: 272.33,511.92 292.02,531.6 311.7,551.29
NetC1_2: C1.2 R2.1 U6.5 | length 63.3
  Bottom Layer w10: U6.5@489.02,847.24 489.02,878.7 490.32,880 R2.1@490.32,910
NetC3_1: C3.1 U1.A2 | length 37.3
  Top Layer w6: U1.A2@633.96,690.72 633.96,702.4
  Top Layer w8: 633.96,702.4 633.96,707.2 645.85,719.09 C3.1@645.85,723.14
NetC7_1: C7.1 U5.20 | length 71.1
  Bottom Layer w10: C7.1@872,1048 872,1085 881.47,1094.47 U5.20@902.2,1094.47
NetC8_1: C8.1 U5.10 | length 42.7
  Bottom Layer w6: U5.10@1051.8,1114.16 1092.84,1114.16 C8.1@1094,1113
NetC13_2: C13.2 U2.5 X2.1 | length 650.4
  Bottom Layer w12: X2.1@326.21,150 C13.2@385,150 385.31,150 385.31,139.69 471,54 873,54 884.96,65.96 U2.5@884.96,106.89
NetC14_2: C14.2 U2.4 X2.2 | length 685.1
  Bottom Layer w12: X2.2@322,55.79 X2.2@322.53,56.31 ; X2.2@323.21,57 C14.2@385,57 385.31,57 385.31,43.69 396,33 910,33 924.33,47.33 U2.4@924.33,106.89
NetC16_1: C16.1 S2.1 U3.2 U3.3 | length 417.1
  Bottom Layer w6: S2.1@158.9,941.42 S2.1@170,930.31
  Bottom Layer w15: 202,695 285.32,695
  Bottom Layer w20: S2.1@170,942 170,930.31 170,727 202,695 ; 285.32,695 288,692.32 C16.1@288,672 288,644.09 292.09,640
NetC18_1: C18.1 U4.D3 | length 37.5
  Bottom Layer w8: U4.D3@816.75,691.62 846.62,691.62 C18.1@852,697
NetD1_1: D1.1 U2.29 | length 481.2
  Top Layer w6: D1.1@789.58,902.19 830,861.76 830,773 882,721 882,591 910,563 v1(910,530)
  Bottom Layer w6: U2.29@884.96,504.96 U2.29@884.96,493.11 898,506.15 898,515 910,527 v1(910,530)
NetD1_2: D1.2 R10.2
NetD2_1: D2.1 U2.28 | length 441.3
  Top Layer w6: v1(890,530) 890,526 906,510 940,510 960,530 960,539 895,604 895,782.49 D2.1@902.14,789.63
  Bottom Layer w4: U2.28@845.59,495.59 865.5,515.5 878.5,515.5 890,527 v1(890,530)
  Bottom Layer w6: U2.28@845.59,493.11 U2.28@845.59,495.59
NetD2_2: D2.2 R22.2
NetD3_1: D3.1 U2.27 | length 256.6
  Top Layer w6: D3.1@943.34,635.87 v1(945,634.2) D3.1@950,629.2
  MidLayer1 w6: v1(870,530) 870,543 882,555 930,555 945,570 v1(945,634.2)
  Bottom Layer w6: U2.27@806.22,493.11 806.22,501.22 825,520 840,520 850,530 v1(870,530)
NetD3_2: D3.2 R23.2
NetD4_1: D4.1 U2.25 | length 235.3
  Top Layer w6: v1(800,540) 800,525 842.89,482.11 D4.1@902.14,482.11
  Bottom Layer w6: U2.25@727.48,493.11 727.48,507.48 749.6,529.6 774.6,529.6 785,540 v1(800,540)
NetD4_2: D4.2 R24.2
NetD5_1: D5.1 U2.21 | length 315.1
  Top Layer w6: v1(540,456.85) 702.27,456.85 D5.1@789.58,369.55
  Bottom Layer w6: v1@540.63,457.48 U2.21@570,457.48
NetD5_2: D5.2 R26.2 | length 8.4
  Top Layer w6: 850,260.52 R26.2@855.97,254.54
NetD6_1: D6.1 U2.20 | length 197.7
  Top Layer w6: v1(540,417.48) 607.52,417.48 635.82,389.18 D6.1@635.82,328.35
  Bottom Layer w6: v1@540.63,418.11 U2.20@570,418.11
NetD6_2: D6.2 R27.2
NetD7_1: D7.1 U2.19 | length 90.9
  Top Layer w6: D7.1@482.06,369.55 490.62,378.11 v1(540,378.11)
  Bottom Layer w6: v1@540.63,378.74 U2.19@570,378.74
NetD7_2: D7.2 R28.2
NetD8_1: D8.1 U2.18 | length 288.6
  Top Layer w6: D8.1@369.5,482.11 369.5,431.96 462.72,338.74 v1(540,338.74)
  Bottom Layer w6: v1@540.63,339.37 U2.18@570,339.37
NetD8_2: D8.2 R29.2
NetD9_1: D9.1 U2.17 | length 705.3
  Top Layer w6: D9.1@328.3,635.87 331.72,632.44 331.72,480.76 342.75,469.73 342.75,422.75 333,413 333,260 355.43,237.57 355.43,215.57 375.96,195.04 420.04,195.04 508.78,283.78 524.41,283.78 v1(540,299.37)
  Bottom Layer w6: v1@540.63,300 U2.17@570,300
NetD9_2: D9.2 R30.2
NetD10_1: D10.1 U2.16 | length 1246.3
  Top Layer w6: D10.1@369.5,789.63 369.5,729.5 340,700 168.04,700 123.73,655.69 123.73,376.27 366,134 469,134 500,165 500,194 540,234 v1(540,260)
  Bottom Layer w6: v1@540.63,260.63 U2.16@570,260.63
NetD10_2: D10.2 R31.2
NetD11_1: D11.1 U2.13 | length 901.2
  Top Layer w6: D11.1@482.06,902.19 424,844.13 424,491.51 515.51,400 550,400 565,385 565,235 540,210 v1(540,145)
  Bottom Layer w6: v1(540,145) 567.52,145 U2.13@570,142.52
NetD11_2: D11.2 R32.2 | length 12
  Top Layer w6: R32.2@415.66,1017.19 424.11,1008.74
NetD12_1: D12.1 U2.24 | length 526.3
  Top Layer w6: D12.1@635.82,943.39 652.61,943.39 740,856 740,708.44 696.35,664.79 696.35,526.35 v1(690,520) v1@687,523
  Bottom Layer w6: U2.24@690,495 v1(690,520)
NetD12_2: D12.2 R25.2
NetD13_2: D13.2 R9.2 | length 259.1
  Top Layer w6: v1(448,640) 468.28,619.72 D13.2@487,619.72
  MidLayer2 w6: v1(409.69,450) 430,470.31 430,632 438,640 v1(448,640)
NetD14_1: D14.1 R33.1 U4.C3 | length 328.7
  Top Layer w6: v1(752,547) 762.72,547 D14.1@800,584.28 D14.1@800,586.75
  MidLayer2 w6: v1(752,547) 778,547 833,602 833,639 816.75,655.25 v3(816.75,675.87)
  Bottom Layer w6: v3(816.75,675.87) 864.87,675.87 875,686 R33.1@891,686
NetD14_2: D14.2 R34.2 | length 195.1
  Top Layer w6: v1(800,619.72) 850,669.72 850,702 v1(864,716)
  MidLayer1 w6: v1(864,716) 881,733 v1(929.31,733)
NetJ1_2: J1.2 R35.1 | length 97
  Bottom Layer w8: J1.2@309.95,947 350.95,988 R35.1@390,988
